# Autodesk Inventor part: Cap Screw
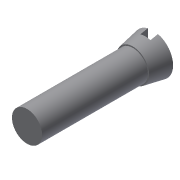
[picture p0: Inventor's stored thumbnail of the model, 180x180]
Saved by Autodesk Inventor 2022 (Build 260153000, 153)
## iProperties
Created: 2002-02
Part Number: Cap Screw
Document SubType Name: Modeling
Designer: ***
Density: 1 g/cm^3
Material: Generic
Mass: 0.736586 g
Surface Area: 5.87035 cm^2
Volume: 0.736586 cm^3
Appearance: Default
Control State: 0
Master: False
Checked Out: False
Shininess: 77.0
Length Units: 11269
Angle Units: 11279
Time Units: 11290
Mass Units: 11283
Length Display Precision: 3
Angle Display Precision: 2
Density: 0.0
Volumn: 0.0
Area: 0.0
PropertySet Name: Model Information
Author: ***
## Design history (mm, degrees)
sketch "Sketch1"
  geometry: L1 (0, 27.83)-(4, 27.83); L2 (4, 27.83)-(3.25, 23.83); L3 (3.25, 23.83)-(0, 23.83); L4 (0, 23.83)-(0, 27.83)
  constraints: 8 end point, 1 horizontal, 1 parallel, 1 perpendicular, 1 point on line
  dimensions: "d2" = 4 distance from line of L1 L2.end; "d5" = 8 diameter of L1.end L4; "d6" = 6.5 diameter of L3.start L4; "d14" = 4 distance of L3.end L1.start
revolve "Revolution1" sketch "Sketch1" stored, may be unused: angle "d7" = 90 deg
sketch "Sketch2"
  geometry: C1 r 3 at (0, 0)
  constraints: 1 centre point
  dimensions: "d8" = 6 diameter of C1
extrude "Extrusion1" join sketch "Sketch2" distance "d9" = 21; taper "d10" = 0 deg
sketch "Sketch3"
  geometry: L1 (-1, 28.967)-(1, 28.967); L2 (1, 28.967)-(1, 26.33); L3 (1, 26.33)-(-1, 26.33); L4 (-1, 26.33)-(-1, 28.967); L5 (-4, 27.83)-(4, 27.83) reference
  constraints: 8 end point, 2 parallel, 1 horizontal, 1 perpendicular
  dimensions: "d11" = 2 distance of L1.start L1.end; "d15" = 1.5 distance between parallel lines of L5 L3
extrude "Extrusion2" cut sketch "Sketch3" extent not by distance; stored distance "d12" = 24; taper "d13" = 0 deg
body "Solid1"
